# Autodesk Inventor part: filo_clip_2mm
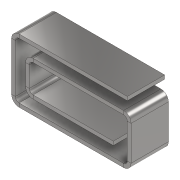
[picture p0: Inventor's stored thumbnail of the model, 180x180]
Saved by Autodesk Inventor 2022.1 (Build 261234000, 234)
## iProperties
Created: 2022-01
Part Number: filo_clip_2mm
Material: Acciaio inossidabile
Document SubType Name: Sheet Metal
Designer: Ryzen5700u
Density: 8 g/cm^3
Sheet Metal Rule: Default_mm
Appearance: Semilucidato
Flat Pattern Width: 0.2 cm
Flat Pattern Length: 3.4 cm
Flat Pattern Area: 0.68 cm^2
Sheet Metal Width: 2,000 mm
Sheet Metal Length: 34,000 mm
Sheet Metal Area: 68,000 mm^2
Mass: 19.881 g
Surface Area: 210.684 cm^2
Volume: 19.881 cm^3
angolo2: 179,9700 gr
angolo1: 179,9700 gr
angolo5: 179,9700 gr
angolo4: 179,9700 gr
angolo3: 179,9700 gr
Author: Ryzen5700u
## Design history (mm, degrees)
node "Flangia contorno2"
  sketch "Schizzo2"
    geometry: L1 (328.088, 73.639)-(388.088, 73.639); L2 (328.088, 73.639)-(298.088, 73.624); L3 (298.088, 73.624)-(238.088, 73.561); L4 (238.088, 73.561)-(215.588, 73.525); L5 (215.588, 73.525)-(163.088, 73.415); L6 (163.088, 73.415)-(148.088, 73.376); L7 (148.088, 73.376)-(103.089, 73.235)
    constraints: 14 end point, 1 horizontal
    dimensions: "d5" = 60 distance of L1.start L1.end; "d31" = 30 distance of L1.start L2.end; "d33" = 179.97 deg angle of L1 L2 (derived); "d34" = 179.97 deg angle of L3 L2 (derived); "d66" = 179.97 deg angle of L3 L4 (derived); "d67" = 22.5 distance of L3.end L4.end; "d68" = 179.97 deg angle of L4 L5 (derived); "d69" = 52.5 distance of L4.end L5.end; "d70" = 179.97 deg angle of L5 L6 (derived); "d71" = 15 distance of L5.end L6.end; "d72" = 179.97 deg angle of L7 L6 (derived); "d73" = 45 distance of L6.end L7.end
node "Solido3"
feature "Piano3" dims "d55" = 2 (derived), "d56" = 2 (derived), "d57" = 1 (derived), "d58" = 4 (derived), "d59" = 2 (derived), "d60" = 20, "d61" = 2, "d62" = 2, "d63" = 8 (derived), "d64" = 2 (derived), "d65" = 2 (derived), "SeamGap" = 0.01
feature "Piega (Bend)2" dims "d55" = 2 (derived), "d56" = 2 (derived), "d57" = 1 (derived), "d58" = 4 (derived), "d59" = 2 (derived), "d61" = 2, "d62" = 2, "SeamGap" = 0.01
feature "Angolo2" dims "d62" = 2, "d63" = 8 (derived), "d64" = 2 (derived), "d65" = 2 (derived)
feature "Definizione1"
other parameters: "Spessore" = 2 (derived), "RaggioPiega" = 2 (= Spessore), "LarghezzaScaricoPiega" = 2 (= Spessore), "ProfonditàScaricoPiega" = 1 (= 0.5 x Spessore), "DimensioniScaricoAngolo" = 8 (= 4 x Spessore), "ResiduoMinimo" = 4 (= 2 x Spessore), "RaggioTransizione" = 2 (= RaggioPiega), "Dimensione_raggio_Jacobi" = 2 (= RaggioPiega), "DimensioneGioco" = 2 (= Spessore), "angolo6" = 31.41069 [user parameter], "DimensioneGioco" = 2, "Dimensione_raggio_Jacobi" = 2, "DimensioniScaricoAngolo" = 8, "LarghezzaScaricoPiega" = 2, "ProfonditàScaricoPiega" = 1, "RaggioPiega" = 2, "RaggioTransizione" = 2, "ResiduoMinimo" = 4, "Spessore" = 2, "angolo2" = 31.41069, "angolo1" = 31.41069, "angolo3" = 31.41069, "angolo4" = 31.41069, "angolo5" = 31.41069, "angolo6" = 31.41069
